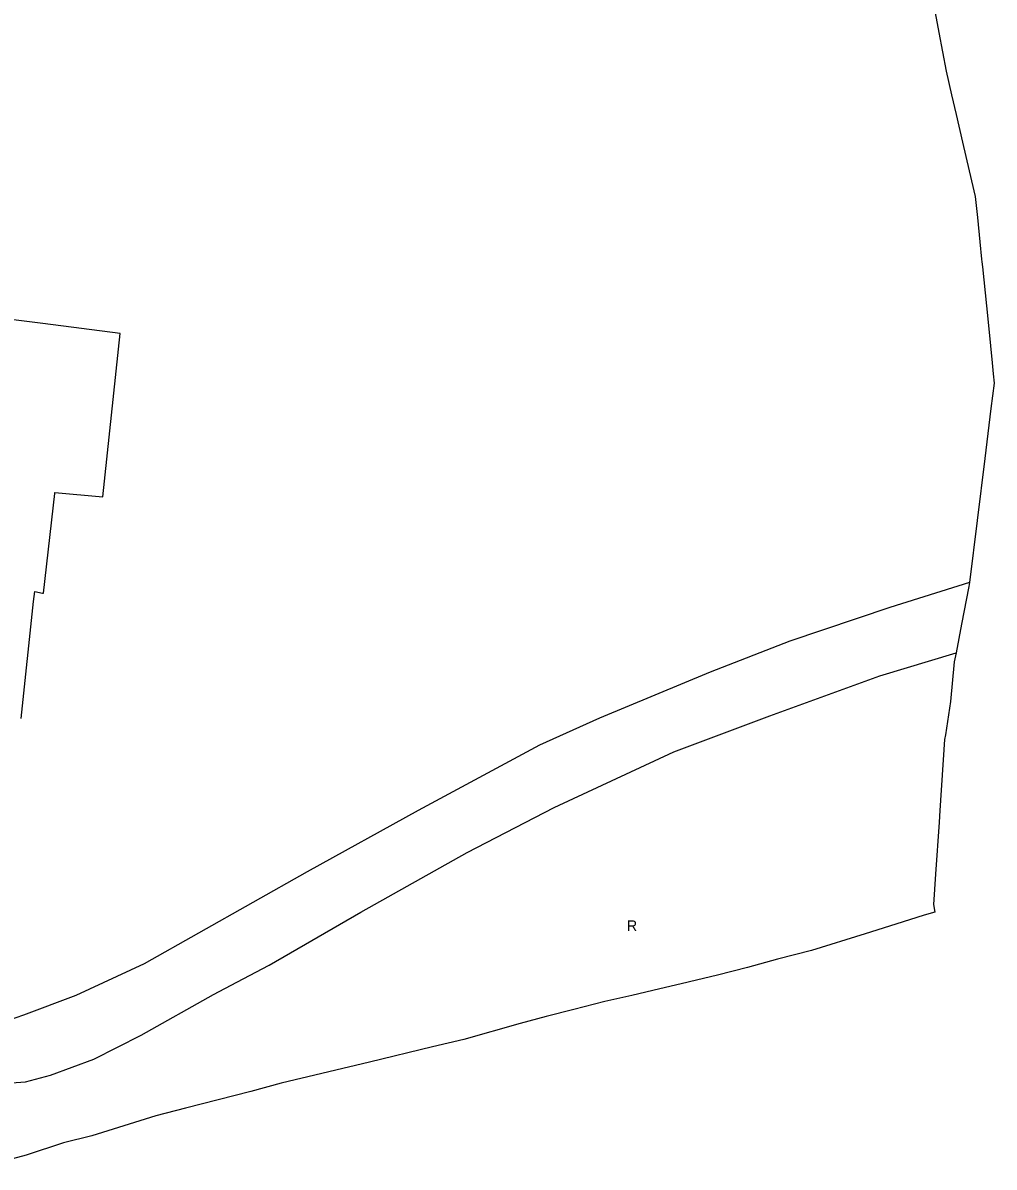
# Model space of a CAD drawing. Extents: x 7435758 to 7439981, y 5550649 to 5554049.
# Drawn here: x 7439051 to 7439523, y 5551161 to 5551717 of the extents above; entities that cross this region are included whole.
import ezdxf

# ---------------------------------------------------------------- set-up
doc = ezdxf.new("R2010")
doc.units = 0
doc.layers.add('linie_rozgraniczające', color=7, linetype='Continuous')
doc.layers.add('oznaczenia_przeznaczen', color=7, linetype='Continuous')

msp = doc.modelspace()

# ---------------------------------------------------------------- linework, layer by layer
at = {"layer": 'linie_rozgraniczające'}
for p, q in [((7439494.09, 5551724.26), (7439496.38, 5551712.14)), ((7439496.38, 5551712.14), (7439499.93, 5551693.34)), ((7439499.93, 5551693.34), (7439502.58, 5551681.92)), ((7439502.58, 5551681.92), (7439504.82, 5551672.32)), ((7439504.82, 5551672.32), (7439507.97, 5551658.81)), ((7439507.97, 5551658.81), (7439511.19, 5551644.92)), ((7439511.19, 5551644.92), (7439514.08, 5551632.52)), ((7439514.08, 5551632.52), (7439515.13, 5551622.21)), ((7439515.13, 5551622.21), (7439516.34, 5551610.41)), ((7439516.34, 5551610.41), (7439517.2, 5551602.06)), ((7439517.2, 5551602.06), (7439517.34, 5551600.76)), ((7439517.34, 5551600.76), (7439517.6, 5551598.21)), ((7439517.6, 5551598.21), (7439519.57, 5551579.27)), ((7439060.87, 5551570.69), (7439011.46, 5551576.97)), ((7439519.57, 5551579.27), (7439520.71, 5551568.08)), ((7439098.47, 5551565.91), (7439060.87, 5551570.69)), ((7439089.93, 5551486.51), (7439098.47, 5551565.91)), ((7439520.71, 5551568.08), (7439522.31, 5551551.62)), ((7439522.31, 5551551.62), (7439522.83, 5551546.28)), ((7439522.83, 5551546.28), (7439523.27, 5551541.74)), ((7439523.27, 5551541.74), (7439521.75, 5551529.36)), ((7439521.75, 5551529.36), (7439518.77, 5551505.17)), ((7439518.77, 5551505.13), (7439511.26, 5551444.8)), ((7439518.77, 5551505.17), (7439518.77, 5551505.13)), ((7439061.13, 5551439.6), (7439066.61, 5551488.08)), ((7439066.61, 5551488.08), (7439066.66, 5551488.5)), ((7439066.66, 5551488.5), (7439089.93, 5551486.51)), ((7439511.25, 5551444.79), (7439472.62, 5551432.62)), ((7439511.02, 5551442.9), (7439507.45, 5551424.59)), ((7439511.26, 5551444.8), (7439511.02, 5551442.9)), ((7439511.26, 5551444.8), (7439511.25, 5551444.79)), ((7439056.33, 5551435.64), (7439056.85, 5551440.41)), ((7439056.85, 5551440.41), (7439060.69, 5551439.68)), ((7439060.69, 5551439.68), (7439061.13, 5551439.6)), ((7439050.2, 5551378.72), (7439056.33, 5551435.64)), ((7439472.62, 5551432.62), (7439423.89, 5551416.23)), ((7439507.45, 5551424.59), (7439504.74, 5551410.66)), ((7439423.89, 5551416.23), (7439385.19, 5551401.28)), ((7439467.79, 5551399.49), (7439504.74, 5551410.66)), ((7439504.74, 5551410.66), (7439503.88, 5551406.28)), ((7439503.88, 5551406.28), (7439502.06, 5551387.04)), ((7439385.19, 5551401.28), (7439331.35, 5551378.93)), ((7439414.25, 5551380.03), (7439467.79, 5551399.49)), ((7439502.06, 5551387.04), (7439499.56, 5551370.7)), ((7439331.35, 5551378.93), (7439302.25, 5551365.81)), ((7439367.62, 5551362.5), (7439414.25, 5551380.03)), ((7439499.56, 5551370.7), (7439499.21, 5551368.43)), ((7439302.25, 5551365.81), (7439243.24, 5551333.99)), ((7439499.21, 5551368.43), (7439496.9, 5551334.03)), ((7439309.45, 5551335.44), (7439367.62, 5551362.5)), ((7439243.24, 5551333.99), (7439189.29, 5551304.22)), ((7439267.12, 5551313.55), (7439309.45, 5551335.44)), ((7439496.9, 5551334.03), (7439496.52, 5551328.38)), ((7439496.52, 5551328.38), (7439494.82, 5551302.97)), ((7439215.4, 5551284.5), (7439267.12, 5551313.55)), ((7439189.29, 5551304.22), (7439110.02, 5551259.43)), ((7439494.82, 5551302.97), (7439493.84, 5551288.34)), ((7439493.84, 5551288.34), (7439494.42, 5551284.61)), ((7439170.76, 5551258.81), (7439215.4, 5551284.5)), ((7439489.34, 5551283.08), (7439475.49, 5551278.79)), ((7439494.42, 5551284.61), (7439489.34, 5551283.08)), ((7439475.49, 5551278.79), (7439460.6, 5551273.99)), ((7439460.6, 5551273.99), (7439434.49, 5551265.95)), ((7439434.49, 5551265.95), (7439417.92, 5551261.67)), ((7439110.02, 5551259.43), (7439076.89, 5551244.09)), ((7439155.05, 5551250.51), (7439170.76, 5551258.81)), ((7439417.92, 5551261.67), (7439403.43, 5551257.64)), ((7439388.72, 5551253.97), (7439375.19, 5551250.68)), ((7439403.43, 5551257.64), (7439388.72, 5551253.97)), ((7439143.76, 5551244.54), (7439155.05, 5551250.51)), ((7439373.86, 5551250.37), (7439360.72, 5551247.3)), ((7439375.19, 5551250.68), (7439373.86, 5551250.37)), ((7439076.89, 5551244.09), (7439051.35, 5551234.41)), ((7439108.54, 5551224.8), (7439143.76, 5551244.54)), ((7439347.2, 5551244), (7439334.05, 5551241.13)), ((7439360.72, 5551247.3), (7439347.2, 5551244)), ((7439318.91, 5551237.21), (7439305.54, 5551233.8)), ((7439334.05, 5551241.13), (7439318.91, 5551237.21)), ((7439051.35, 5551234.41), (7439043.9, 5551231.93)), ((7439305.54, 5551233.8), (7439292.79, 5551230.48)), ((7439292.79, 5551230.48), (7439265.43, 5551222.61)), ((7439085.55, 5551213.16), (7439108.54, 5551224.8)), ((7439265.43, 5551222.61), (7439250.31, 5551219.11)), ((7439250.31, 5551219.11), (7439219.61, 5551211.6)), ((7439064.47, 5551205.31), (7439085.55, 5551213.16)), ((7439219.61, 5551211.6), (7439176.71, 5551201.4)), ((7439052.32, 5551202.01), (7439064.47, 5551205.31)), ((7439027.83, 5551200.3), (7439052.32, 5551202.01)), ((7439176.71, 5551201.4), (7439161.92, 5551197.44)), ((7439161.92, 5551197.44), (7439130.16, 5551189.28)), ((7439130.16, 5551189.28), (7439115.82, 5551185.47)), ((7439115.82, 5551185.47), (7439084.67, 5551175.85)), ((7439084.67, 5551175.85), (7439070.8, 5551172.49)), ((7439070.8, 5551172.49), (7439052.63, 5551166.35)), ((7439052.63, 5551166.35), (7439030.35, 5551160.62))]:
    msp.add_line(p, q, dxfattribs=at)

# ---------------------------------------------------------------- texts
at = {"layer": 'oznaczenia_przeznaczen'}
msp.add_text('R', height=5.2, dxfattribs=at).set_placement((7439344.74, 5551275.38))

doc.saveas('drawing.dxf')
